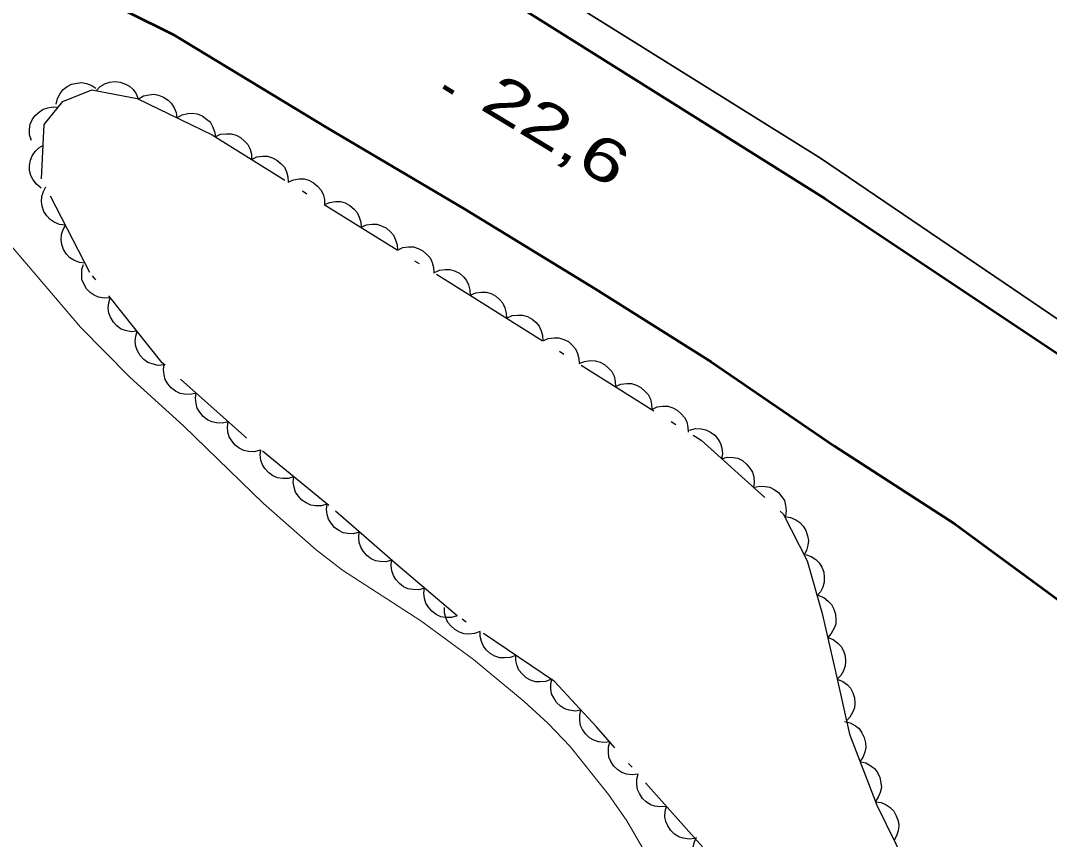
# Model space of a CAD drawing. Extents: x 356765 to 358572, y 5103174 to 5104650.
# Drawn here: x 357555.78 to 357591.77, y 5103689.59 to 5103718.22 of the extents above; entities that cross this region are included whole.
import ezdxf

# ---------------------------------------------------------------- set-up
doc = ezdxf.new("R2010")
doc.units = 0
doc.header["$LTSCALE"] = 0.6
doc.linetypes.add('DOT_DASHED', pattern=[7.7, 5, -1.2, 0.3, -1.2])
for name, color, linetype, lineweight in [('2', 7, 'Continuous', 13), ('21', 7, 'Continuous', 53), ('22', 7, 'Continuous', 35), ('3', 7, 'Continuous', 140), ('44', 7, 'Continuous', 25)]:
    doc.layers.add(name, color=color, linetype=linetype, lineweight=lineweight)

msp = doc.modelspace()

# ---------------------------------------------------------------- linework, layer by layer
at = {"layer": '2'}
msp.add_lwpolyline([(357577.53, 5103689.3), (357576.99, 5103690.25), (357576.35, 5103691.16), (357575, 5103692.84), (357574.23, 5103693.65), (357573.4, 5103694.42), (357571.62, 5103695.88), (357569.78, 5103697.24), (357567.04, 5103699.01), (357566.12, 5103699.72), (357564.28, 5103701.34), (357561.48, 5103704.05), (357559.6, 5103705.76), (357557.88, 5103707.51), (357550.58, 5103716.05)], dxfattribs=at)
at = {"layer": '21'}
for points in [[(357338.61, 5103773.13), (357340.11, 5103772.62), (357343.3, 5103771.76), (357350.78, 5103769.83), (357368.94, 5103766.05), (357392.09, 5103762.41), (357416.79, 5103758.21), (357441.26, 5103754.15), (357468.58, 5103749.26), (357504.23, 5103742.99), (357523.34, 5103739.7), (357536.22, 5103737.01), (357542.95, 5103734.88), (357550.23, 5103731.38), (357559.17, 5103726.82), (357569.84, 5103720.84), (357583.91, 5103712.01), (357595.28, 5103704.43), (357600.89, 5103700.45), (357609.42, 5103694), (357620.2, 5103685.76)], [(357511.52, 5103734.46), (357526.07, 5103731.29), (357532.07, 5103730.08), (357536.9, 5103728.84), (357545.61, 5103725.43), (357556.4, 5103720.09), (357561.12, 5103717.74), (357566.51, 5103714.48), (357571.32, 5103711.63), (357575.88, 5103708.84), (357579.94, 5103706.29), (357584.25, 5103703.34), (357588.47, 5103700.62), (357593.04, 5103697.26), (357597.8, 5103693.8), (357604.89, 5103688.51)]]:
    msp.add_lwpolyline(points, dxfattribs=at)
at = {"layer": '22'}
msp.add_lwpolyline([(357468.95, 5103750.64), (357513.48, 5103742.84), (357531.11, 5103739.41), (357539.54, 5103737.41), (357545.5, 5103734.97), (357554.23, 5103730.63), (357567.35, 5103723.66), (357583.76, 5103713.42), (357597.55, 5103704.05), (357603.13, 5103700.17), (357610.19, 5103694.78), (357623.39, 5103684.71)], dxfattribs=at)
at = {"layer": '3'}
msp.add_line((357570.57, 5103715.92), (357570.91, 5103715.71), dxfattribs=at)
at = {"layer": '44', "linetype": 'DOT_DASHED'}
msp.add_lwpolyline([(357579.63, 5103689.33), (357575.92, 5103693.53), (357574.46, 5103695.12), (357571.05, 5103697.41), (357569.06, 5103699.1), (357566.56, 5103701.27), (357563.61, 5103703.69), (357560.74, 5103706.26), (357558.21, 5103709.42), (357556.52, 5103712.69), (357556.61, 5103714.59), (357557.26, 5103715.39), (357558.27, 5103715.8), (357559.86, 5103715.5), (357562.48, 5103714.23), (357571.48, 5103708.64), (357579.58, 5103703.55), (357582.45, 5103700.98), (357583.29, 5103699.34), (357583.82, 5103697.49), (357584.33, 5103695.26), (357584.77, 5103693.27), (357585.73, 5103690.79), (357586.92, 5103688.38)], dxfattribs=at)
at = {"layer": '44'}
for points in [[(357557.03, 5103715.3), (357557.07, 5103715.5), (357557.17, 5103715.68), (357557.27, 5103715.81), (357557.41, 5103715.92), (357557.57, 5103716), (357557.76, 5103716.04), (357557.92, 5103716.06), (357558.09, 5103716.03), (357558.27, 5103715.96), (357558.42, 5103715.86)], [(357558.43, 5103715.77), (357558.57, 5103715.92), (357558.75, 5103716.02), (357558.91, 5103716.07), (357559.08, 5103716.09), (357559.27, 5103716.07), (357559.45, 5103716), (357559.59, 5103715.93), (357559.72, 5103715.81), (357559.83, 5103715.66), (357559.9, 5103715.49)], [(357559.9, 5103715.48), (357560.08, 5103715.59), (357560.28, 5103715.63), (357560.44, 5103715.65), (357560.61, 5103715.62), (357560.78, 5103715.55), (357560.94, 5103715.44), (357561.06, 5103715.33), (357561.15, 5103715.18), (357561.22, 5103715.01), (357561.25, 5103714.83)], [(357556.16, 5103714.03), (357556.1, 5103714.23), (357556.1, 5103714.43), (357556.12, 5103714.6), (357556.19, 5103714.76), (357556.29, 5103714.91), (357556.44, 5103715.04), (357556.57, 5103715.13), (357556.74, 5103715.18), (357556.92, 5103715.21), (357557.1, 5103715.2)], [(357561.25, 5103714.83), (357561.43, 5103714.93), (357561.63, 5103714.98), (357561.79, 5103714.99), (357561.96, 5103714.96), (357562.13, 5103714.9), (357562.29, 5103714.78), (357562.41, 5103714.68), (357562.5, 5103714.52), (357562.57, 5103714.35), (357562.6, 5103714.17)], [(357562.59, 5103714.16), (357562.78, 5103714.25), (357562.98, 5103714.27), (357563.15, 5103714.27), (357563.32, 5103714.22), (357563.48, 5103714.14), (357563.62, 5103714.01), (357563.73, 5103713.89), (357563.81, 5103713.73), (357563.86, 5103713.55), (357563.86, 5103713.37)], [(357556.5, 5103712.37), (357556.34, 5103712.5), (357556.22, 5103712.66), (357556.14, 5103712.81), (357556.1, 5103712.98), (357556.09, 5103713.16), (357556.13, 5103713.35), (357556.19, 5103713.5), (357556.29, 5103713.65), (357556.42, 5103713.78), (357556.58, 5103713.87)], [(357563.86, 5103713.37), (357564.05, 5103713.46), (357564.26, 5103713.48), (357564.42, 5103713.48), (357564.59, 5103713.43), (357564.75, 5103713.34), (357564.9, 5103713.22), (357565.01, 5103713.1), (357565.08, 5103712.94), (357565.13, 5103712.76), (357565.14, 5103712.58)], [(357565.14, 5103712.58), (357565.33, 5103712.66), (357565.53, 5103712.69), (357565.7, 5103712.69), (357565.86, 5103712.64), (357566.03, 5103712.55), (357566.17, 5103712.43), (357566.28, 5103712.31), (357566.36, 5103712.15), (357566.41, 5103711.97), (357566.41, 5103711.79)], [(357557.35, 5103711.07), (357557.15, 5103711.1), (357556.96, 5103711.18), (357556.82, 5103711.27), (357556.7, 5103711.4), (357556.6, 5103711.55), (357556.54, 5103711.74), (357556.51, 5103711.9), (357556.53, 5103712.07), (357556.58, 5103712.25), (357556.67, 5103712.41)], [(357566.41, 5103711.79), (357566.6, 5103711.87), (357566.8, 5103711.9), (357566.97, 5103711.9), (357567.14, 5103711.85), (357567.3, 5103711.76), (357567.45, 5103711.63), (357567.56, 5103711.51), (357567.63, 5103711.35), (357567.68, 5103711.18), (357567.69, 5103711)], [(357567.69, 5103711), (357567.88, 5103711.08), (357568.08, 5103711.11), (357568.24, 5103711.11), (357568.41, 5103711.05), (357568.58, 5103710.97), (357568.72, 5103710.84), (357568.83, 5103710.72), (357568.9, 5103710.56), (357568.95, 5103710.38), (357568.96, 5103710.2)], [(357558.04, 5103709.74), (357557.84, 5103709.77), (357557.65, 5103709.85), (357557.51, 5103709.93), (357557.39, 5103710.06), (357557.29, 5103710.22), (357557.23, 5103710.4), (357557.2, 5103710.56), (357557.22, 5103710.74), (357557.27, 5103710.92), (357557.35, 5103711.07)], [(357568.96, 5103710.2), (357569.15, 5103710.29), (357569.35, 5103710.32), (357569.52, 5103710.31), (357569.69, 5103710.26), (357569.85, 5103710.18), (357569.99, 5103710.05), (357570.11, 5103709.93), (357570.18, 5103709.77), (357570.23, 5103709.59), (357570.24, 5103709.41)], [(357558.92, 5103708.53), (357558.71, 5103708.52), (357558.51, 5103708.56), (357558.36, 5103708.62), (357558.22, 5103708.72), (357558.09, 5103708.85), (357558, 5103709.02), (357557.93, 5103709.17), (357557.92, 5103709.35), (357557.93, 5103709.53), (357557.98, 5103709.7)], [(357570.24, 5103709.41), (357570.43, 5103709.5), (357570.63, 5103709.52), (357570.79, 5103709.52), (357570.96, 5103709.47), (357571.13, 5103709.39), (357571.27, 5103709.26), (357571.38, 5103709.14), (357571.45, 5103708.98), (357571.5, 5103708.8), (357571.51, 5103708.62)], [(357571.51, 5103708.62), (357571.7, 5103708.71), (357571.9, 5103708.73), (357572.07, 5103708.73), (357572.24, 5103708.68), (357572.4, 5103708.59), (357572.54, 5103708.46), (357572.65, 5103708.34), (357572.72, 5103708.18), (357572.77, 5103708), (357572.78, 5103707.82)], [(357559.86, 5103707.36), (357559.65, 5103707.34), (357559.45, 5103707.39), (357559.3, 5103707.44), (357559.15, 5103707.55), (357559.03, 5103707.68), (357558.93, 5103707.85), (357558.87, 5103708), (357558.85, 5103708.18), (357558.87, 5103708.36), (357558.92, 5103708.53)], [(357572.78, 5103707.82), (357572.97, 5103707.91), (357573.17, 5103707.93), (357573.34, 5103707.93), (357573.51, 5103707.88), (357573.67, 5103707.79), (357573.81, 5103707.67), (357573.92, 5103707.54), (357573.99, 5103707.38), (357574.04, 5103707.21), (357574.05, 5103707.03)], [(357560.8, 5103706.19), (357560.59, 5103706.17), (357560.39, 5103706.22), (357560.23, 5103706.27), (357560.09, 5103706.38), (357559.96, 5103706.51), (357559.87, 5103706.68), (357559.81, 5103706.83), (357559.79, 5103707), (357559.81, 5103707.19), (357559.86, 5103707.36)], [(357574.05, 5103707.03), (357574.24, 5103707.11), (357574.44, 5103707.13), (357574.61, 5103707.13), (357574.78, 5103707.08), (357574.94, 5103707), (357575.08, 5103706.87), (357575.19, 5103706.75), (357575.26, 5103706.59), (357575.31, 5103706.41), (357575.32, 5103706.23)], [(357561.92, 5103705.2), (357561.72, 5103705.15), (357561.52, 5103705.16), (357561.36, 5103705.19), (357561.2, 5103705.27), (357561.05, 5103705.38), (357560.93, 5103705.53), (357560.84, 5103705.67), (357560.8, 5103705.84), (357560.78, 5103706.02), (357560.81, 5103706.2)], [(357575.32, 5103706.23), (357575.51, 5103706.31), (357575.71, 5103706.34), (357575.88, 5103706.33), (357576.05, 5103706.28), (357576.21, 5103706.2), (357576.35, 5103706.07), (357576.46, 5103705.95), (357576.54, 5103705.79), (357576.58, 5103705.61), (357576.59, 5103705.43)], [(357576.59, 5103705.43), (357576.78, 5103705.51), (357576.98, 5103705.54), (357577.15, 5103705.54), (357577.32, 5103705.48), (357577.48, 5103705.4), (357577.62, 5103705.27), (357577.73, 5103705.15), (357577.81, 5103704.99), (357577.85, 5103704.81), (357577.86, 5103704.63)], [(357563.04, 5103704.2), (357562.84, 5103704.15), (357562.64, 5103704.16), (357562.47, 5103704.19), (357562.32, 5103704.27), (357562.17, 5103704.38), (357562.05, 5103704.53), (357561.96, 5103704.67), (357561.92, 5103704.84), (357561.9, 5103705.02), (357561.92, 5103705.2)], [(357577.86, 5103704.63), (357578.05, 5103704.72), (357578.25, 5103704.74), (357578.42, 5103704.74), (357578.59, 5103704.69), (357578.75, 5103704.6), (357578.89, 5103704.47), (357579, 5103704.35), (357579.08, 5103704.19), (357579.12, 5103704.01), (357579.13, 5103703.83)], [(357564.16, 5103703.2), (357563.96, 5103703.15), (357563.75, 5103703.16), (357563.59, 5103703.19), (357563.43, 5103703.27), (357563.29, 5103703.38), (357563.17, 5103703.53), (357563.08, 5103703.67), (357563.03, 5103703.84), (357563.02, 5103704.02), (357563.04, 5103704.2)], [(357579.18, 5103703.9), (357579.39, 5103703.96), (357579.59, 5103703.95), (357579.75, 5103703.92), (357579.91, 5103703.84), (357580.06, 5103703.73), (357580.18, 5103703.58), (357580.26, 5103703.44), (357580.31, 5103703.27), (357580.33, 5103703.08), (357580.3, 5103702.9)], [(357565.34, 5103702.27), (357565.14, 5103702.21), (357564.94, 5103702.21), (357564.77, 5103702.24), (357564.61, 5103702.31), (357564.46, 5103702.41), (357564.33, 5103702.56), (357564.24, 5103702.69), (357564.19, 5103702.86), (357564.16, 5103703.04), (357564.18, 5103703.22)], [(357580.3, 5103702.9), (357580.5, 5103702.96), (357580.71, 5103702.95), (357580.87, 5103702.92), (357581.03, 5103702.84), (357581.17, 5103702.72), (357581.29, 5103702.57), (357581.38, 5103702.44), (357581.43, 5103702.27), (357581.44, 5103702.08), (357581.42, 5103701.9)], [(357566.5, 5103701.32), (357566.3, 5103701.26), (357566.1, 5103701.26), (357565.93, 5103701.28), (357565.77, 5103701.36), (357565.62, 5103701.46), (357565.49, 5103701.61), (357565.4, 5103701.74), (357565.35, 5103701.91), (357565.32, 5103702.09), (357565.34, 5103702.27)], [(357581.42, 5103701.9), (357581.62, 5103701.95), (357581.82, 5103701.94), (357581.99, 5103701.91), (357582.14, 5103701.83), (357582.29, 5103701.72), (357582.41, 5103701.57), (357582.5, 5103701.44), (357582.54, 5103701.27), (357582.56, 5103701.08), (357582.54, 5103700.9)], [(357567.63, 5103700.34), (357567.43, 5103700.28), (357567.23, 5103700.29), (357567.07, 5103700.32), (357566.91, 5103700.4), (357566.76, 5103700.5), (357566.64, 5103700.65), (357566.55, 5103700.79), (357566.5, 5103700.96), (357566.48, 5103701.14), (357566.5, 5103701.32)], [(357582.5, 5103700.88), (357582.71, 5103700.85), (357582.9, 5103700.77), (357583.04, 5103700.68), (357583.15, 5103700.55), (357583.25, 5103700.4), (357583.31, 5103700.21), (357583.34, 5103700.05), (357583.32, 5103699.88), (357583.27, 5103699.7), (357583.19, 5103699.54)], [(357568.77, 5103699.36), (357568.56, 5103699.3), (357568.36, 5103699.31), (357568.2, 5103699.34), (357568.04, 5103699.41), (357567.89, 5103699.52), (357567.77, 5103699.67), (357567.68, 5103699.81), (357567.63, 5103699.98), (357567.61, 5103700.16), (357567.63, 5103700.34)], [(357569.91, 5103698.38), (357569.71, 5103698.32), (357569.5, 5103698.33), (357569.34, 5103698.36), (357569.18, 5103698.43), (357569.03, 5103698.54), (357568.91, 5103698.68), (357568.82, 5103698.82), (357568.77, 5103698.99), (357568.74, 5103699.17), (357568.76, 5103699.35)], [(357583.23, 5103699.56), (357583.43, 5103699.49), (357583.59, 5103699.38), (357583.71, 5103699.27), (357583.8, 5103699.11), (357583.87, 5103698.94), (357583.89, 5103698.75), (357583.89, 5103698.59), (357583.84, 5103698.42), (357583.76, 5103698.25), (357583.64, 5103698.12)], [(357571.05, 5103697.41), (357570.85, 5103697.35), (357570.65, 5103697.36), (357570.48, 5103697.38), (357570.32, 5103697.46), (357570.17, 5103697.57), (357570.05, 5103697.71), (357569.96, 5103697.85), (357569.91, 5103698.02), (357569.89, 5103698.2), (357569.91, 5103698.38)], [(357583.67, 5103698.13), (357583.87, 5103698.05), (357584.03, 5103697.92), (357584.14, 5103697.81), (357584.23, 5103697.65), (357584.28, 5103697.47), (357584.29, 5103697.28), (357584.29, 5103697.12), (357584.22, 5103696.96), (357584.13, 5103696.79), (357584.01, 5103696.66)], [(357571.86, 5103696.87), (357571.66, 5103696.79), (357571.46, 5103696.77), (357571.3, 5103696.78), (357571.13, 5103696.84), (357570.97, 5103696.93), (357570.83, 5103697.06), (357570.72, 5103697.18), (357570.65, 5103697.34), (357570.61, 5103697.52), (357570.61, 5103697.7)], [(357573.1, 5103696.03), (357572.91, 5103695.95), (357572.71, 5103695.94), (357572.54, 5103695.94), (357572.37, 5103696), (357572.21, 5103696.09), (357572.07, 5103696.22), (357571.97, 5103696.35), (357571.9, 5103696.51), (357571.86, 5103696.69), (357571.86, 5103696.87)], [(357584.01, 5103696.66), (357584.2, 5103696.59), (357584.36, 5103696.46), (357584.48, 5103696.34), (357584.56, 5103696.19), (357584.62, 5103696.01), (357584.63, 5103695.82), (357584.62, 5103695.66), (357584.56, 5103695.49), (357584.47, 5103695.33), (357584.34, 5103695.2)], [(357574.35, 5103695.2), (357574.15, 5103695.12), (357573.95, 5103695.1), (357573.79, 5103695.11), (357573.62, 5103695.16), (357573.46, 5103695.25), (357573.32, 5103695.39), (357573.21, 5103695.51), (357573.15, 5103695.67), (357573.1, 5103695.85), (357573.1, 5103696.03)], [(357575.38, 5103694.12), (357575.18, 5103694.08), (357574.97, 5103694.11), (357574.82, 5103694.16), (357574.67, 5103694.25), (357574.53, 5103694.38), (357574.43, 5103694.54), (357574.35, 5103694.69), (357574.33, 5103694.86), (357574.33, 5103695.05), (357574.37, 5103695.22)], [(357584.34, 5103695.2), (357584.54, 5103695.12), (357584.7, 5103695), (357584.81, 5103694.88), (357584.89, 5103694.72), (357584.95, 5103694.55), (357584.96, 5103694.35), (357584.95, 5103694.19), (357584.88, 5103694.03), (357584.79, 5103693.87), (357584.67, 5103693.74)], [(357576.4, 5103693.01), (357576.19, 5103692.98), (357575.99, 5103693.01), (357575.83, 5103693.06), (357575.68, 5103693.15), (357575.55, 5103693.27), (357575.44, 5103693.44), (357575.37, 5103693.58), (357575.34, 5103693.75), (357575.34, 5103693.94), (357575.38, 5103694.12)], [(357584.6, 5103693.72), (357584.8, 5103693.67), (357584.98, 5103693.57), (357585.11, 5103693.47), (357585.21, 5103693.32), (357585.29, 5103693.16), (357585.33, 5103692.97), (357585.35, 5103692.81), (357585.31, 5103692.64), (357585.24, 5103692.46), (357585.14, 5103692.32)], [(357577.38, 5103691.88), (357577.17, 5103691.85), (357576.97, 5103691.88), (357576.81, 5103691.93), (357576.67, 5103692.03), (357576.53, 5103692.16), (357576.43, 5103692.32), (357576.36, 5103692.47), (357576.34, 5103692.64), (357576.34, 5103692.83), (357576.39, 5103693)], [(357585.14, 5103692.32), (357585.34, 5103692.27), (357585.52, 5103692.17), (357585.65, 5103692.07), (357585.75, 5103691.93), (357585.83, 5103691.76), (357585.87, 5103691.57), (357585.89, 5103691.41), (357585.85, 5103691.24), (357585.78, 5103691.07), (357585.68, 5103690.92)], [(357578.37, 5103690.75), (357578.17, 5103690.73), (357577.97, 5103690.76), (357577.81, 5103690.81), (357577.66, 5103690.91), (357577.53, 5103691.03), (357577.43, 5103691.2), (357577.36, 5103691.34), (357577.33, 5103691.52), (357577.34, 5103691.7), (357577.38, 5103691.88)], [(357579.37, 5103689.63), (357579.16, 5103689.6), (357578.96, 5103689.64), (357578.8, 5103689.68), (357578.65, 5103689.78), (357578.52, 5103689.91), (357578.42, 5103690.07), (357578.35, 5103690.22), (357578.32, 5103690.39), (357578.33, 5103690.58), (357578.37, 5103690.75)], [(357585.67, 5103690.91), (357585.88, 5103690.88), (357586.06, 5103690.8), (357586.2, 5103690.71), (357586.32, 5103690.58), (357586.41, 5103690.42), (357586.47, 5103690.24), (357586.5, 5103690.08), (357586.48, 5103689.9), (357586.42, 5103689.72), (357586.33, 5103689.57)], [(357580.2, 5103688.39), (357579.99, 5103688.4), (357579.8, 5103688.47), (357579.65, 5103688.54), (357579.53, 5103688.67), (357579.42, 5103688.81), (357579.35, 5103688.99), (357579.3, 5103689.15), (357579.31, 5103689.33), (357579.35, 5103689.51), (357579.42, 5103689.67)]]:
    msp.add_lwpolyline(points, dxfattribs=at)

# ---------------------------------------------------------------- texts
at = {"layer": '3', "width": 1.4}
msp.add_text('22,6   ', height=1.5, rotation=328.822, dxfattribs=at).set_placement((357571.8, 5103715.16))

doc.saveas('drawing.dxf')
